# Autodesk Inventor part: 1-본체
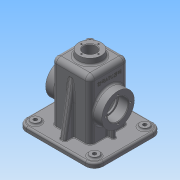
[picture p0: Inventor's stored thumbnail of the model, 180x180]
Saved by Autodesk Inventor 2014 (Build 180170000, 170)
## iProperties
Created: 2015-12
Part Number: 1-본체
Material: Generic
Document SubType Name: Modeling
Designer: Administrator
Density: 1 g/cm^3
Appearance: Default
Author: Administrator
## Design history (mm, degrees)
sketch "스케치1"
  geometry: L1 (50, -57.5)-(-50, -57.5); L2 (-65, -42.5)-(-65, 42.5); L3 (-50, 57.5)-(50, 57.5); L4 (65, 42.5)-(65, -42.5); L5 (65, -57.5)-(-65, 57.5); L6 (-65, -57.5)-(65, 57.5); A1 r 15 centre (-50, 42.5) between (-50, 57.5) and (-65, 42.5); A2 r 15 centre (-50, -42.5) between (-65, -42.5) and (-50, -57.5); A3 r 15 centre (50, -42.5) between (50, -57.5) and (65, -42.5); A4 r 15 centre (50, 42.5) between (65, 42.5) and (50, 57.5); 1 further point
  constraints: 12 end point, 8 point on circle, 8 point on line, 8 tangent, 4 centre point, 3 equal radius, 2 midpoint, 2 parallel, 1 horizontal, 1 perpendicular
  dimensions: "d0" = 115 distance of L6.start L5.end; "d1" = 130 distance of L5.end L6.end; "d2" = 15 radius of A1
extrude "돌출1" new body sketch "스케치1" distance "d3" = 10; taper "d4" = 0 deg
sketch "스케치2"
  geometry: L1 (24.5, -32.5)-(-24.5, -32.5); L2 (-32.5, -24.5)-(-32.5, 24.5); L3 (-24.5, 32.5)-(24.5, 32.5); L4 (32.5, 24.5)-(32.5, -24.5); L5 (32.5, -32.5)-(-32.5, 32.5); L6 (-32.5, -32.5)-(32.5, 32.5); A1 r 8 centre (-24.5, 24.5) between (-24.5, 32.5) and (-32.5, 24.5); A2 r 8 centre (24.5, 24.5) between (32.5, 24.5) and (24.5, 32.5); A3 r 8 centre (24.5, -24.5) between (24.5, -32.5) and (32.5, -24.5); A4 r 8 centre (-24.5, -24.5) between (-32.5, -24.5) and (-24.5, -32.5); 1 further point
  constraints: 12 end point, 8 point on circle, 8 point on line, 8 tangent, 4 centre point, 3 equal radius, 2 midpoint, 2 parallel, 1 horizontal, 1 perpendicular
  dimensions: "d5" = 65 distance of L5.end L6.end; "d6" = 65 distance of L6.start L5.end; "d7" = 8 radius of A1
extrude "돌출2" join sketch "스케치2" distance "d8" = 100; taper "d9" = 0 deg
sketch "스케치3"
  geometry: L1 (50, 57.5)-(-50, 57.5) reference; L2 (-65, 42.5)-(-65, -42.5) reference; L3 (-50, -57.5)-(50, -57.5) reference; L4 (65, -42.5)-(65, 42.5) reference; L5 (-50, 52.5)-(50, 52.5); L6 (60, 42.5)-(60, -42.5); L7 (50, -52.5)-(-50, -52.5); L8 (-60, -42.5)-(-60, 42.5); A1 r 15 centre (-50, 42.5) between (-50, 57.5) and (-65, 42.5) reference; A2 r 15 centre (-50, -42.5) between (-65, -42.5) and (-50, -57.5) reference; A3 r 15 centre (50, -42.5) between (50, -57.5) and (65, -42.5) reference; A4 r 15 centre (50, 42.5) between (65, 42.5) and (50, 57.5) reference; A5 r 10 centre (50, 42.5) between (60, 42.5) and (50, 52.5); A6 r 10 centre (50, -42.5) between (50, -52.5) and (60, -42.5); A7 r 10 centre (-50, -42.5) between (-60, -42.5) and (-50, -52.5); A8 r 10 centre (-50, 42.5) between (-50, 52.5) and (-60, 42.5); 1 further point
  constraints: 8 end point, 8 point on circle, 4 centre point, 7 other
  dimensions: "d10" = 5 distance between parallel lines of L2 L8
extrude "돌출3" cut sketch "스케치3" distance "d11" = 2; taper "d12" = 0 deg
node "작업 평면1"
sketch "스케치4"
  geometry: L1 (0, 85)-(0, 0) reference; L2 (0, 0)-(0, -15) reference; L3 (0, 100)-(0, 85) reference; L4 (0, 10)-(-100, 10) reference; L5 (0, -5)-(-85.069, 10); L6 (8, -15)-(0, -15) reference; L7 (0, 75)-(-100, 75) reference; L8 (-85.069, 10)-(-85.069, 75); L9 (-85.069, 75)-(0, 90); L10 (8, 100)-(0, 100) reference; 1 further point
  constraints: 6 end point, 4 point on line, 1 perpendicular
  dimensions: "d15" = 10 distance of L3.start L9.end; "d16" = 10 deg angle of L9 L10; "d17" = 10 deg angle of L5 L6
extrude "돌출4" join sketch "스케치4" stored distance "d18" = 10; taper "d19" = 0 deg
sketch "스케치5"
  geometry: L1 (24.5, -27.5)-(-24.5, -27.5); L2 (-27.5, -24.5)-(-27.5, 24.5); L3 (-24.5, 27.5)-(24.5, 27.5); L4 (27.5, 24.5)-(27.5, -24.5); L5 (27.5, -27.5)-(-27.5, 27.5); L6 (-27.5, -27.5)-(27.5, 27.5); A1 r 3 centre (-24.5, 24.5) between (-24.5, 27.5) and (-27.5, 24.5); A2 r 3 centre (24.5, 24.5) between (27.5, 24.5) and (24.5, 27.5); A3 r 3 centre (24.5, -24.5) between (24.5, -27.5) and (27.5, -24.5); A4 r 3 centre (-24.5, -24.5) between (-27.5, -24.5) and (-24.5, -27.5); 1 further point
  constraints: 12 end point, 8 point on circle, 8 point on line, 8 tangent, 4 centre point, 3 equal radius, 2 midpoint, 2 parallel, 1 horizontal, 1 perpendicular
  dimensions: "d20" = 55 distance of L5.end L6.end; "d21" = 55 distance of L6.start L5.end; "d22" = 3 radius of A1
extrude "돌출5" cut sketch "스케치5" distance "d23" = 105; taper "d24" = 0 deg
sketch "스케치6"
  geometry: C1 r 20 at (0, 0); 1 further point
  constraints: 1 centre point, 1 coincident
  dimensions: "d25" = 40 diameter of C1
extrude "돌출6" join sketch "스케치6" distance "d26" = 10; taper "d27" = -5 deg
node "작업 평면2"
sketch "스케치7"
  geometry: L1 (10, 67)-(10, -18) reference; L2 (8, -18)-(8, 67) reference; C1 r 27.5 at (-45, 24.5); 2 further points
  constraints: 1 centre point, 1 horizontal alignment, 1 midpoint
  dimensions: "d29" = 55 diameter of C1; "d31" = 55 distance from line of L1 C1.centre
extrude "돌출7" join sketch "스케치7" stored distance "d32" = 10; taper "d33" = 0 deg
hole "구멍1" diameter "d36" = 30; stored, may be unused: countersink angle "d40" = 90 deg, drill point angle "d42" = 118 deg; dims "d37" = 6, "d38" = 35, "d39" = 17, "d41" = 8, "d43" = 10, "d44" = 10
sketch "스케치8"
  geometry: C1 r 17.5 at (0, 0) reference; C2 r 27.5 at (0, 0) reference; A1 r 21 centre (0, 0) between (0, -21) and (-21, 0); 3 further points
  constraints: 4 point on circle, 2 horizontal alignment, 2 vertical alignment, 1 centre point, 1 coincident
  dimensions: "d45" = 42 diameter of A1
hole "구멍2" sketch "스케치8" at (0, -21), (-21, 0), (0, 21), (21, 0) diameter "d46" = 3.242; stored, may be unused: countersink angle "d50" = 90 deg, drill point angle "d52" = 118 deg; dims "d47" = 8, "d48" = 42, "d49" = 17, "d51" = 10
hole "구멍3" diameter "d55" = 21; stored, may be unused: countersink angle "d59" = 90 deg, drill point angle "d61" = 118 deg; dims "d53" = 10, "d54" = 10, "d56" = 8, "d57" = 42, "d58" = 17, "d60" = 10
sketch "스케치9"
  geometry: C1 r 10.5 at (0, 0) reference; C2 r 19.125 at (0, 0) reference; A1 r 14.5 centre (0, 0) between (14.5, 0) and (0, 14.5); 2 further points
  constraints: 4 point on circle, 2 horizontal alignment, 2 vertical alignment, 1 centre point, 1 coincident
  dimensions: "d62" = 29 diameter of A1
hole "구멍4" sketch "스케치9" at (14.5, 0), (0, 14.5), (-14.5, 0), (0, -14.5) diameter "d63" = 2.459; stored, may be unused: countersink angle "d67" = 90 deg, drill point angle "d69" = 118 deg; dims "d64" = 7, "d65" = 4, "d66" = 2, "d68" = 9
sketch "스케치10"
  geometry: C1 r 7.5 at (-50, 42.5); C2 r 7.5 at (50, 42.5); C3 r 7.5 at (-50, -42.5); C4 r 7.5 at (50, -42.5); A1 r 15 centre (-50, 42.5) between (-50, 57.5) and (-65, 42.5) reference; A2 r 15 centre (-50, -42.5) between (-65, -42.5) and (-50, -57.5) reference; A3 r 15 centre (50, -42.5) between (50, -57.5) and (65, -42.5) reference; A4 r 15 centre (50, 42.5) between (65, 42.5) and (50, 57.5) reference; 1 further point
  constraints: 4 centre point, 4 coincident, 1 equal radius
  dimensions: "d70" = 15 diameter of C1; "d71" = 15 diameter of C2; "d72" = 15 diameter of C3
extrude "돌출8" join sketch "스케치10" distance "d73" = 3; taper "d74" = 0 deg
sketch "스케치11"
  geometry: C1 r 7.5 at (0, 0) reference; C2 r 7.5 at (100, 0) reference; C3 r 7.5 at (100, -85) reference; C4 r 7.5 at (0, -85) reference; 5 further points
  constraints: 4 coincident
hole "구멍5" sketch "스케치11" at (0, 0), (100, 0), (100, -85), (0, -85) diameter "d75" = 6; stored, may be unused: countersink angle "d79" = 90 deg, drill point angle "d81" = 118 deg; dims "d76" = 6, "d77" = 4, "d78" = 2, "d80" = 9
fillet "모깎기1" dims "d82" = 8
fillet "모깎기5" dims "d91" = 3
node "작업 평면4"
sketch "스케치13"
  geometry: L1 (17.5, 0)-(17.5, 32.51) reference; L2 (17.5, 17.5)-(2.5, 17.5) reference; L3 (100, 0)-(0, 0) reference; L4 (7.5, 19)-(7.5, 0); L5 (22.5, -10)-(22.5, 95) reference; L6 (7.5, 19)-(19.04, 19); L7 (19.04, 19)-(19.04, 0); 1 further point
  constraints: 6 end point, 3 perpendicular, 2 point on line
  dimensions: "d92" = 15 distance between parallel lines of L4 L5; "d93" = 11.54026 distance of L4.start L6.end; "d94" = 19 distance of L6.end L7.end
extrude "돌출10" join sketch "스케치13" stored distance "d95" = 6; taper "d96" = 0 deg
fillet "모깎기6" dims "d97" = 3
fillet "모깎기7" dims "d98" = 1
fillet "모깎기8" dims "d99" = 3
fillet "모깎기9" dims "d100" = 0.3
fillet "모깎기10" dims "d101" = 3
chamfer "모따기1" distance "d102" = 1; stored, may be unused: second distance "d103" = 2, angle "d104" = 45 deg
sketch "스케치14"
  geometry: L1 (-65, -19.125)-(-65, 19.125) reference; 3 further points
  constraints: 1 horizontal alignment, 1 midpoint, 1 other
  dimensions: "d105" = 26 distance of point (-39, 0) point (-65, 0)
feature "엠보싱1" sketch "스케치14" dims "d5" = 65, "d6" = 65, "d7" = 8, "d106" = 0.5, "d107" = 0
fillet "모깎기11" dims "d108" = 3
fillet "모깎기12" dims "d109" = 3
node "솔리드1"
mirror "대칭1"
mirror "대칭3"
other parameters: "d28" = 15
